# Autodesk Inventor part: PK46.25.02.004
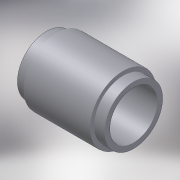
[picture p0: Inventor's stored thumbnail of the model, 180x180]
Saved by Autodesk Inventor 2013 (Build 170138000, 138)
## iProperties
Created: 2005-04
Part Number: PK46.25.02.004
Material: Steel, Mild
Document SubType Name: Modeling
Designer: salex
Manufacturer: Standard
Standards Organization: Custom
Density: 7.86 g/cm^3
Mass: 14190.7 g
Surface Area: 1977.24 cm^2
Volume: 1805.43 cm^3
Author: salex
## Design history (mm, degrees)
sketch "Эскиз1"
  geometry: L1 (0, 0)-(150.126, 0); L2 (0, 70)-(0, 57.5); L3 (0, 57.5)-(210, 57.5); L4 (210, 57.5)-(210, 70); L5 (210, 70)-(185, 70); L6 (185, 70)-(185, 80); L7 (185, 80)-(25, 80); L8 (25, 80)-(25, 70); L9 (25, 70)-(0, 70)
  constraints: 18 end point, 4 perpendicular, 3 collinear, 3 parallel, 1 horizontal, 1 other
  dimensions: "d0" = 0 distance from line of L1.start L2; "d1" = 115 diameter of L3 L1; "d2" = 140 diameter of L9 L1; "d3" = 160 diameter of L7 L1; "d4" = 160 distance of L6.end L7.end; "d5" = 210 distance between parallel lines of L4 L2
revolve "Вращение1" sketch "Эскиз1" stored, may be unused: angle "d6" = 90 deg
body "Solid1"
